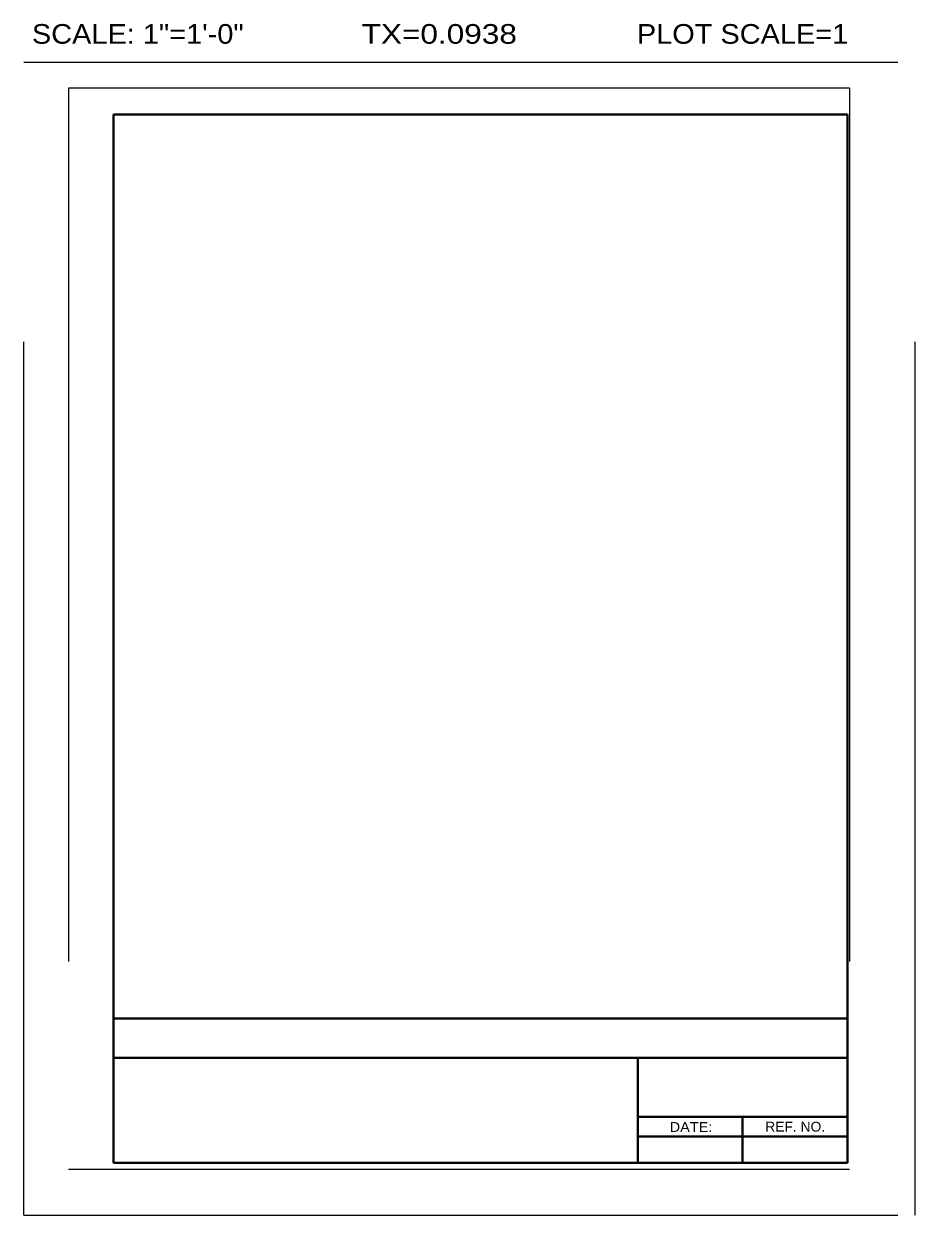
# Model space of a CAD drawing. Extents: x 16.44 to 16.542, y -10.866 to -10.73.
import ezdxf
from ezdxf.enums import TextEntityAlignment as Align

# ---------------------------------------------------------------- set-up
doc = ezdxf.new("R2010")
doc.units = 0
doc.header["$LTSCALE"] = 0.0009
doc.linetypes.add('DOTTED', pattern=[1.5, 0.3, -1.2])
doc.layers.add('59', color=7, linetype='Continuous')
doc.layers.add('9', color=7, linetype='Continuous')
for name, color, linetype, lineweight in [('61', 7, 'DOTTED', 13), ('62', 7, 'DOTTED', 13), ('63', 7, 'Continuous', 40)]:
    doc.layers.add(name, color=color, linetype=linetype, lineweight=lineweight)

msp = doc.modelspace()

# ---------------------------------------------------------------- linework, layer by layer
at = {"layer": '61'}
for p, q in [((16.5345, -10.73697), (16.4451, -10.73697)), ((16.4451, -10.73697), (16.4451, -10.86078)), ((16.5345, -10.73697), (16.5345, -10.86078)), ((16.5345, -10.86078), (16.4451, -10.86078))]:
    msp.add_line(p, q, dxfattribs=at)
at = {"layer": '62'}
for p, q in [((16.44, -10.866), (16.44, -10.734)), ((16.44, -10.734), (16.542, -10.734)), ((16.542, -10.866), (16.542, -10.734)), ((16.44, -10.866), (16.542, -10.866))]:
    msp.add_line(p, q, dxfattribs=at)
at = {"layer": '63'}
for p, q in [((16.45025, -10.74), (16.45025, -10.86)), ((16.45025, -10.74), (16.53425, -10.74)), ((16.53425, -10.74), (16.53425, -10.86)), ((16.45025, -10.8435), (16.53425, -10.8435)), ((16.45025, -10.848), (16.53425, -10.848)), ((16.51025, -10.86), (16.51025, -10.848)), ((16.51025, -10.85475), (16.53425, -10.85475)), ((16.52225, -10.86), (16.52225, -10.85475)), ((16.51025, -10.857), (16.53425, -10.857)), ((16.45025, -10.86), (16.53425, -10.86))]:
    msp.add_line(p, q, dxfattribs=at)

# ---------------------------------------------------------------- texts
at = {"layer": '59'}
for s, width, p in [('REF. NO.', 1.05, (16.52827, -10.85643)), ('DATE:', 1.1, (16.51635, -10.85647))]:
    msp.add_text(s, height=0.001126, dxfattribs=dict(at, width=width)).set_placement(p, align=Align.CENTER)
at = {"layer": '9'}
for s, width, p in [('SCALE: 1"=1\'-0"', 1.1, (16.45304, -10.73189)), ('TX=0.0938', 1.2, (16.48754, -10.73189)), ('PLOT SCALE=1', 1.1, (16.52225, -10.73189))]:
    msp.add_text(s, height=0.00225, dxfattribs=dict(at, width=width)).set_placement(p, align=Align.CENTER)

doc.saveas('drawing.dxf')
